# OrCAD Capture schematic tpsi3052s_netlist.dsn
size A
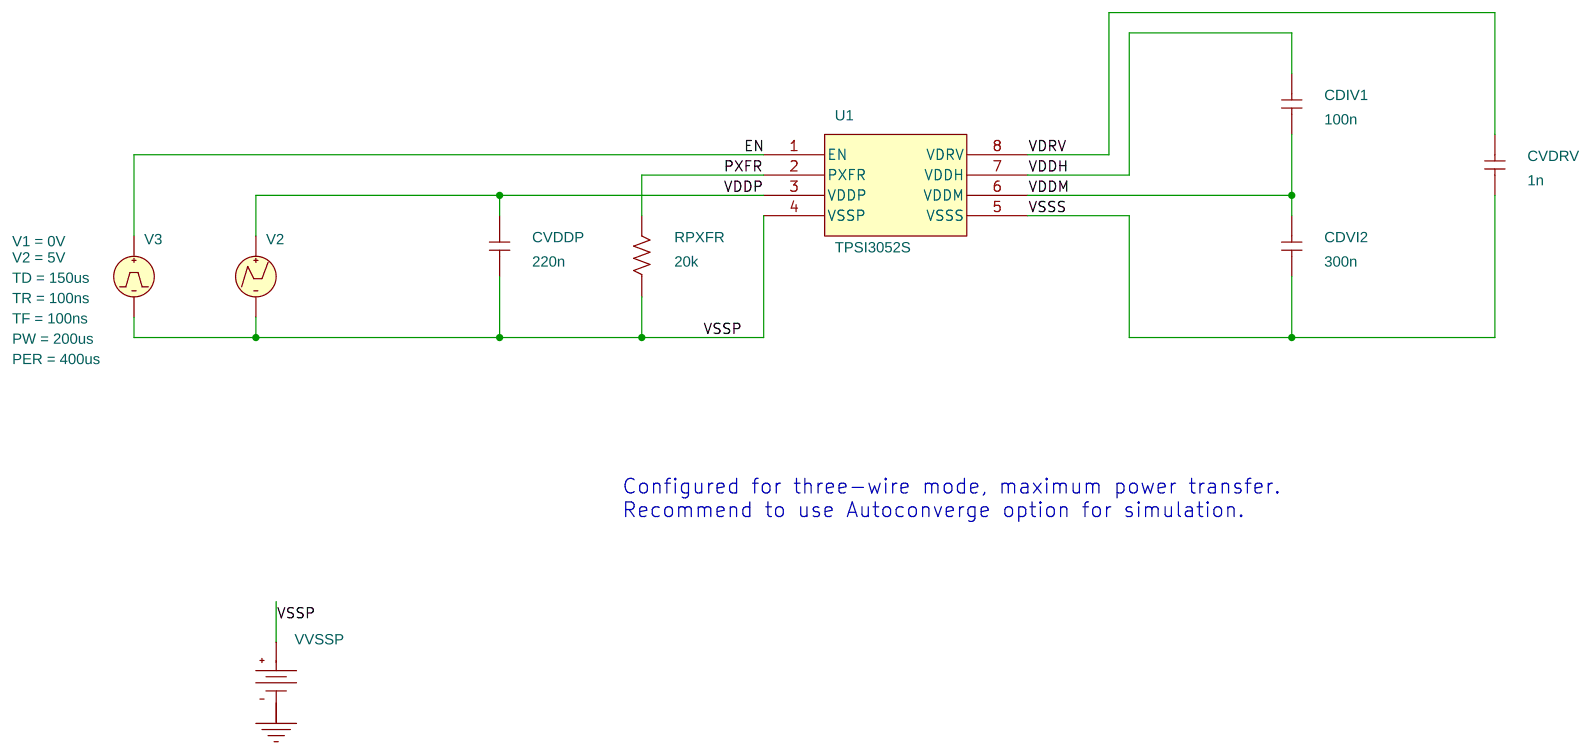
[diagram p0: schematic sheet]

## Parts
CDIV1  100n  [cap196]
CDVI2  300n  [cap196]
CVDDP  220n  [cap196]
CVDRV  1n  [cap196]
RPXFR  20k  [AXRC05]
U1  TPSI3052S
V2  VPWL
V3  VPULSE
VVSSP  VDC

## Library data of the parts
CDIV1 CDVI2 CVDDP CVDRV = C
RPXFR = R
U1 = TPSI3052S
V2 = VPWL: T1: 0us; T2: 5us; T3: 5.1us; V1: 0V; V2: 0V; V3: 5V
V3 = VPULSE: PER: 400us; PW: 200us; TD: 150us; TF: 100ns; TR: 100ns; V1: 0V; V2: 5V
VVSSP = VDC

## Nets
VDDH: CDIV1.2 U1.7(VDDH)
VDDM: CDIV1.1 CDVI2.2 U1.6(VDDM)
VDDP: CVDDP.2 U1.3(VDDP) V2.1(+)
VSSP: CVDDP.1 RPXFR.1 U1.4(VSSP) V2.2(-) V3.2(-) VVSSP.0(+)
VSSS: CDVI2.1 CVDRV.1 U1.5(VSSS)
0: VVSSP.1(-)
EN: U1.1(EN) V3.1(+)
PXFR: RPXFR.2 U1.2(PXFR)
VDRV: CVDRV.2 U1.8(VDRV)

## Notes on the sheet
- Configured for three-wire mode, maximum power transfer.
  Recommend to use Autoconverge option for simulation.
